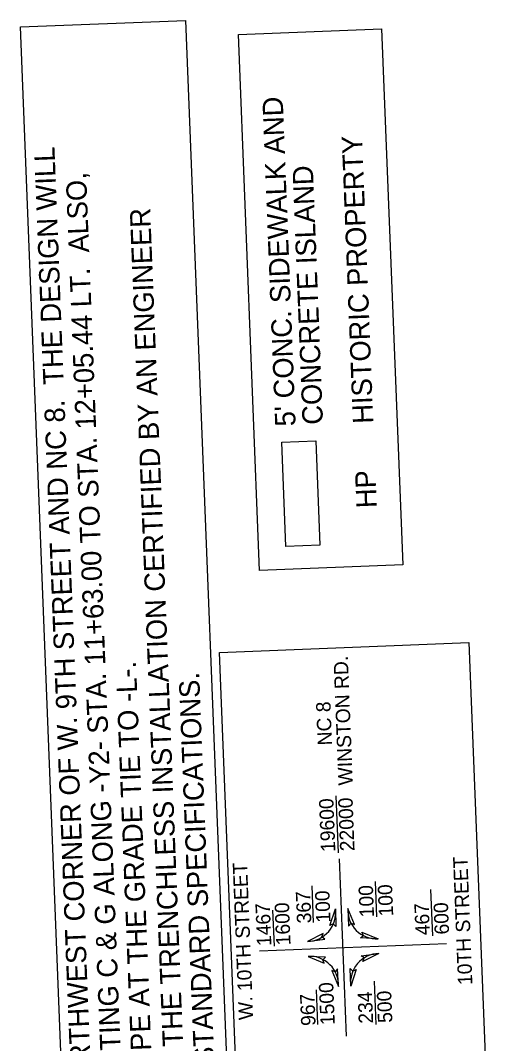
# Model space of a CAD drawing. Extents: x 1627861 to 1629601, y 761281 to 766239.
# Drawn here: x 1628820.5 to 1628982.5, y 762489 to 762839.7 of the extents above; entities that cross this region are included whole.
import ezdxf

# ---------------------------------------------------------------- set-up
doc = ezdxf.new("R2010")
doc.units = 0
for name, color, linetype in [('Default', 7, 'Continuous'), ('Exist Other Culture Sign Leader', 7, 'Continuous'), ('Exist Utilities Power UG Cable SUE LOS B Cogo Point CELL', 7, 'Continuous'), ('Exist Utilities Water UG Line SUE LOS B Cogo Point CELL', 7, 'Continuous'), ('Exist Utilities Water Valve CELL', 7, 'Continuous')]:
    doc.layers.add(name, color=color, linetype=linetype)

msp = doc.modelspace()

# ---------------------------------------------------------------- linework, layer by layer
at = {"layer": 'Default'}
for p, q in [((1628929.66, 762554.36), (1628928.89, 762573.89)), ((1628932.43, 762491.48), (1628930.03, 762552.36)), ((1628921.12, 762530.48), (1628920.62, 762543.07)), ((1628942.79, 762532.41), (1628942.31, 762544.53)), ((1628961.98, 762525.98), (1628961.36, 762541.77)), ((1628907.68, 762522.41), (1628907.19, 762534.72)), ((1628902.51, 762520.79), (1628966.67, 762523.32)), ((1628942.64, 762495.57), (1628942.05, 762510.43)), ((1628922.54, 762495.54), (1628922.07, 762507.42))]:
    msp.add_line(p, q, dxfattribs=at)
msp.add_lwpolyline([(1628896.98, 762417.98), (1628888.89, 762623.06), (1628974.43, 762626.43), (1628982.52, 762421.35)], close=True, dxfattribs=at)
for centre, start, end in [((1628918.8, 762533.88), 271.2141, 7.3945), ((1628942.71, 762534.82), 177.1219, 273.3023), ((1628919.78, 762509.01), 357.1219, 93.3023), ((1628943.69, 762509.96), 91.2141, 187.3945)]:
    msp.add_arc(centre, 9.89, start, end, dxfattribs=at)
at = {"layer": 'Exist Other Culture Sign Leader'}
for points in [[(1628853.64, 761998.34), (1628820.55, 762837.45), (1628877.21, 762839.68), (1628910.3, 762000.57)], [(1628902.59, 762651.14), (1628895.35, 762834.85), (1628944.47, 762836.78), (1628951.71, 762653.07)]]:
    msp.add_lwpolyline(points, close=True, dxfattribs=at)
at = {"layer": 'Exist Utilities Water UG Line SUE LOS B Cogo Point CELL'}
for points in [[(1628926.69, 762529.45), (1628928.61, 762535.15), (1628928.73, 762529.1), (1628927.81, 762530.01)], [(1628935.15, 762529.77), (1628932.83, 762535.32), (1628933.13, 762529.27), (1628933.99, 762530.24)], [(1628924.36, 762526.76), (1628919.01, 762523.99), (1628925.02, 762524.79), (1628923.97, 762525.57)], [(1628937.7, 762527.21), (1628943.28, 762524.95), (1628937.22, 762525.19), (1628938.19, 762526.06)], [(1628925.22, 762518.58), (1628919.21, 762518.89), (1628924.8, 762516.54), (1628924.29, 762517.74)], [(1628937.5, 762519.1), (1628943.48, 762519.85), (1628938.07, 762517.11), (1628938.49, 762518.33)], [(1628927.36, 762514.08), (1628929.66, 762508.52), (1628929.38, 762514.57), (1628928.52, 762513.6)], [(1628935.74, 762514.41), (1628933.88, 762508.68), (1628933.69, 762514.74), (1628934.63, 762513.84)]]:
    msp.add_lwpolyline(points, close=True, dxfattribs=at)
at = {"layer": 'Exist Utilities Water Valve CELL'}
msp.add_lwpolyline([(1628911.61, 762659.42), (1628910.2, 762695.16), (1628921.84, 762695.62), (1628923.25, 762659.88)], close=True, dxfattribs=at)

# ---------------------------------------------------------------- texts
at = {"layer": 'Default'}
for s, height, p in [('WINSTON RD.', 4.9438, (1628934.61, 762577.59)), ('NC 8', 4.944, (1628927.48, 762591.29)), ('22000', 4.944, (1628935.19, 762555.04)), ('19600', 4.944, (1628928.61, 762554.78)), ('10TH STREET', 4.9438, (1628975.62, 762509.16)), ('W. 10TH STREET', 4.9438, (1628900.42, 762497.18)), ('100', 4.944, (1628941.88, 762532.39)), ('100', 4.944, (1628948.47, 762532.65)), ('367', 4.944, (1628920.37, 762530.29)), ('100', 4.944, (1628926.95, 762530.55)), ('1467', 4.944, (1628906.66, 762522.51)), ('1600', 4.944, (1628913.24, 762522.77)), ('467', 4.944, (1628961.04, 762526.21)), ('600', 4.944, (1628967.63, 762526.47)), ('1500', 4.944, (1628928.41, 762495.41)), ('234', 4.944, (1628941.58, 762495.94)), ('500', 4.944, (1628948.16, 762496.2)), ('967', 4.944, (1628921.82, 762495.15))]:
    msp.add_text(s, height=height, rotation=92.2582, dxfattribs=at).set_placement(p)
at = {"layer": 'Exist Other Culture Sign Leader'}
for s, p in [("5' CONC. SIDEWALK AND", (1628914.97, 762700.69)), ('HISTORIC PROPERTY', (1628941.63, 762701.59)), ('CONCRETE ISLAND', (1628924.36, 762701.24)), ('HP', (1628942.83, 762672.66))]:
    msp.add_text(s, height=7, rotation=92.2582, dxfattribs=at).set_placement(p)
at = {"layer": 'Exist Utilities Power UG Cable SUE LOS B Cogo Point CELL'}
for s, p in [('1.)  TO MINIMIZE IMPACTS TO THE HISTORIC PROPERTY AND STONE RETAINING WALL ON THE NORTHWEST CORNER OF W. 9TH STREET AND NC 8.  THE DESIGN WILL', (1628862.33, 762032.65)), ('INCOPORATE OVERLAY AND MILLING.  THE PROPOSED PAVEMENT WILL NEED TO TIE TO THE EXISTING C & G ALONG -Y2- STA. 11+63.00 TO STA. 12+05.44 LT.  ALSO,', (1628872.82, 762033.06)), ('2.)  PRIOR TO COMMENCING WORK ON ANY TRENCHLESS INSTALLATION, PROVIDE A DESIGN FOR THE TRENCHLESS INSTALLATION CERTIFIED BY AN ENGINEER', (1628894.29, 762033.91)), ('THE -Y2- OVERLAY PAVEMENT WILL NEED TO TRANSITION TO MATCH THE PROPOSED CROSS SLOPE AT THE GRADE TIE TO -L-.', (1628883.32, 762033.48)), ('LICENSED BY THE STATE OF NORTH CAROLINA, AS REQUIRED BY SUBARTICLE 1550-3(B) OF THE STANDARD SPECIFICATIONS.', (1628904.78, 762034.33))]:
    msp.add_text(s, height=7, rotation=92.2582, dxfattribs=at).set_placement(p)

doc.saveas('drawing.dxf')
